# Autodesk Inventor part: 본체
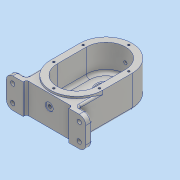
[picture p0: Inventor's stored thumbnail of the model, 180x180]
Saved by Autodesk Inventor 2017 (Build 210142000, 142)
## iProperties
Part Number: 본체
Material: 알루미늄 6061
Document SubType Name: Modeling
Designer: MRC
Density: 2.7 g/cm^3
Appearance: 알루미늄 - 평지
Mass: 756.746 g
Surface Area: 581.68 cm^2
Volume: 280.276 cm^3
Author: MRC
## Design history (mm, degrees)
sketch "스케치1"
  geometry: L1 (0, 0)-(0, -87); L2 (-40, 0)-(-40, -82); L3 (40, -82)-(40, 0); L4 (-40, -82)-(-61, -82); L5 (-61, -82)-(-61, -92); L6 (-61, -92)-(-35, -92); L7 (-35, -92)-(-35, -87); L8 (-35, -87)-(35, -87); L9 (35, -87)-(35, -92); L10 (35, -92)-(61, -92); L11 (61, -92)-(61, -82); L12 (61, -82)-(40, -82); A1 r 40 centre (0, 0) between (40, 0) and (-40, 0); 1 further point
  constraints: 26 end point, 4 parallel, 4 vertical, 2 collinear, 2 horizontal, 2 midpoint, 2 perpendicular, 2 point on circle, 2 tangent, 1 centre point
  dimensions: "d15" = 40 radius of A1; "d16" = 10 distance of L10.end L11.end; "d17" = 92 distance from line of L10 L1.start; "d18" = 70 distance of L7.end L8.end; "d19" = 122 distance between parallel lines of L11 L5; "d20" = 5 distance between parallel lines of L6 L8; "d21" = 61 distance from line of point (0, -43.5) L5
extrude "돌출1" new body sketch "스케치1" distance "d22" = 46; taper "d23" = 0 deg
sketch "스케치2"
  geometry: L1 (0, 0)-(0, -45); L2 (-40, 0)-(-40, -45); L3 (40, -45)-(40, 0); A1 r 40 centre (0, 0) between (40, 0) and (-40, 0) reference; A2 r 40 centre (0, 0) between (40, 0) and (-40, 0); A3 r 40 centre (0, -45) between (-40, -45) and (40, -45); 1 further point
  constraints: 8 end point, 4 point on circle, 4 tangent, 2 centre point, 1 concentric, 1 midpoint, 1 parallel, 1 vertical
  dimensions: "d24" = 45 distance of L1.end L1.start
extrude "돌출2" join sketch "스케치2" distance "d25" = 3; taper "d26" = 0 deg
sketch "스케치3"
  geometry: L1 (0, 0)-(0, -45); L2 (-26, 0)-(-26, -45); L3 (26, -45)-(26, 0); A1 r 40 centre (0, 0) between (40, 0) and (-40, 0) reference; A2 r 26 centre (0, 0) between (26, 0) and (-26, 0); A3 r 26 centre (0, -45) between (-26, -45) and (26, -45); 1 further point
  constraints: 8 end point, 4 point on circle, 4 tangent, 2 centre point, 1 midpoint, 1 parallel, 1 vertical
  dimensions: "d27" = 26 radius of A2; "d28" = 45 distance of L1.start L1.end
extrude "돌출3" join sketch "스케치3" distance "d29" = 11; taper "d30" = 0 deg
sketch "스케치4"
  geometry: L1 (-26, 0)-(-26, -45) reference; L2 (26, -45)-(26, 0) reference; L3 (-26, -45)-(-26, 0) reference; L4 (-26, -30)-(26, -30); A1 r 26 centre (0, 0) between (26, 0) and (-26, 0) reference
  constraints: 2 end point, 2 point on line, 1 perpendicular
  dimensions: "d31" = 30 distance from line of A1.centre L4
extrude "돌출4" cut sketch "스케치4" distance "d32" = 3; taper "d33" = 0 deg
sketch "스케치5"
  geometry: L1 (0, 0)-(0, -45); L2 (-30, 0)-(-30, -45); L3 (30, -45)-(30, 0); A1 r 40 centre (0, -45) between (-40, -45) and (40, -45) reference; A2 r 40 centre (0, 0) between (40, 0) and (-40, 0) reference; A3 r 30 centre (0, 0) between (30, 0) and (-30, 0); A4 r 30 centre (0, -45) between (-30, -45) and (30, -45); 1 further point
  constraints: 8 end point, 4 point on circle, 4 tangent, 2 centre point, 1 midpoint, 1 parallel, 1 vertical
  dimensions: "d34" = 30 radius of A3
extrude "돌출5" cut sketch "스케치5" distance "d35" = 41; taper "d36" = 0 deg
hole "구멍1" diameter "d39" = 20; stored, may be unused: countersink angle "d43" = 90 deg, drill point angle "d45" = 0 deg; dims "d40" = 6, "d41" = 28, "d42" = 8, "d44" = 12, "d46" = 10, "d47" = 10
hole "구멍2" diameter "d50" = 22; stored, may be unused: countersink angle "d54" = 90 deg, drill point angle "d56" = 0 deg; dims "d48" = 10, "d49" = 10, "d51" = 6, "d52" = 28, "d53" = 8, "d55" = 100
sketch "스케치6"
  geometry: C1 r 11 at (0, 0) reference; C2 r 14 at (0, 0); A1 r 26 centre (0, 0) between (26, 0) and (-26, 0) reference
  constraints: 1 centre point, 1 coincident
  dimensions: "d57" = 28 diameter of C2
extrude "돌출6" cut sketch "스케치6" distance "d58" = 4; taper "d59" = 0 deg
sketch "스케치8"
  geometry: L1 (0, 0)-(0, -45); L2 (35, 0)-(35, -45); L3 (-35, -45)-(-35, 0); A1 r 40 centre (0, -45) between (-40, -45) and (40, -45) reference; A2 r 40 centre (0, 0) between (40, 0) and (-40, 0) reference; A3 r 35 centre (0, 0) between (35, 0) and (-35, 0); A4 r 35 centre (0, -45) between (-35, -45) and (35, -45); 7 further points
  constraints: 8 end point, 6 point on circle, 4 coincident, 4 tangent, 2 centre point, 1 midpoint, 1 parallel, 1 vertical
  dimensions: "d60" = 35 radius of A3
hole "구멍3" sketch "스케치8" at (0, 35), (-35, 0), (35, 0), (35, -45), (-35, -45), (0, -80) diameter "d61" = 3.242; stored, may be unused: countersink angle "d65" = 90 deg, drill point angle "d67" = 118 deg; dims "d62" = 8, "d63" = 28, "d64" = 8, "d66" = 10
node "작업 평면1"
sketch "스케치9"
  geometry: C1 r 6 at (0, 28); 1 further point
  constraints: 1 centre point
  dimensions: "d69" = 12 diameter of C1; "d70" = 28 distance of C1.centre point (0, 0)
extrude "돌출7" join sketch "스케치9" stored distance "d71" = 4; taper "d72" = 0 deg
sketch "스케치10"
  geometry: C1 r 6 at (0, 0) reference; 2 further points
  constraints: 1 coincident
hole "구멍4" sketch "스케치10" at (0, 0) diameter "d73" = 4.917; stored, may be unused: countersink angle "d77" = 90 deg, drill point angle "d79" = 0 deg; dims "d74" = 12, "d75" = 28, "d76" = 8, "d78" = 17.1
sketch "스케치12"
  geometry: L1 (0, 0)-(70, 0) reference; L2 (75, 49)-(-5, 49) reference; 3 further points
  constraints: 1 midpoint, 1 vertical alignment
  dimensions: "d88" = 21 distance from line of point (35, 28) L2
hole "구멍5" sketch "스케치12" at (35, 28) diameter "d81" = 4.917; stored, may be unused: countersink angle "d85" = 90 deg, drill point angle "d87" = 0 deg; dims "d82" = 12, "d83" = 12, "d84" = 1, "d86" = 17.1
fillet "모깎기1" dims "d89" = 10
hole "구멍6" diameter "d92" = 6.6; stored, may be unused: countersink angle "d96" = 90 deg, drill point angle "d98" = 0 deg; dims "d90" = 10, "d91" = 10, "d93" = 12, "d94" = 11, "d95" = 2, "d97" = 17.1
hole "구멍7" diameter "d101" = 6.6; stored, may be unused: countersink angle "d105" = 90 deg, drill point angle "d107" = 0 deg; dims "d99" = 10, "d100" = 10, "d102" = 12, "d103" = 11, "d104" = 2, "d106" = 17.1
hole "구멍8" diameter "d110" = 6.6; stored, may be unused: countersink angle "d114" = 90 deg, drill point angle "d116" = 0 deg; dims "d108" = 10, "d109" = 10, "d111" = 12, "d112" = 11, "d113" = 2, "d115" = 17.1
hole "구멍9" diameter "d119" = 6.6; stored, may be unused: countersink angle "d123" = 90 deg, drill point angle "d125" = 0 deg; dims "d117" = 10, "d118" = 10, "d120" = 12, "d121" = 11, "d122" = 2, "d124" = 17.1
fillet "모깎기3" dims "d130" = 3
fillet "모깎기2" dims "d126" = 3
chamfer "모따기1" distance "d127" = 1; stored, may be unused: second distance "d128" = 2, angle "d129" = 45 deg
fillet "모깎기4" dims "d131" = 3
fillet "모깎기5" dims "d132" = 0.3
chamfer "모따기2" distance "d133" = 1; stored, may be unused: second distance "d134" = 2, angle "d135" = 45 deg
fillet "모깎기6" dims "d136" = 3
fillet "모깎기7" dims "d137" = 3
sketch "스케치13"
  geometry: L1 (-51, -92)-(-61, -92) reference; 1 further point
  constraints: 1 other
  dimensions: "d138" = 12 distance from line of L1 point (-0.116, -80)
feature "엠보싱1" sketch "스케치13" dims "d15" = 40, "d16" = 10, "d17" = 92, "d18" = 70, "d19" = 122, "d20" = 5, "d21" = 61, "d24" = 45, "d139" = 0.5, "d140" = 0
sketch "스케치14"
  geometry: A1 r 26 centre (0, 0) between (26, 0) and (-26, 0) reference; 1 further point
  constraints: 1 vertical alignment
  dimensions: "d141" = 20 distance of point (0, 20) A1.centre
hole "구멍10" sketch "스케치14" at (0, 20) diameter "d142" = 3.242; stored, may be unused: countersink angle "d146" = 90 deg, drill point angle "d148" = 118 deg; dims "d143" = 8, "d144" = 11, "d145" = 2, "d147" = 10
fillet "모깎기8" dims "d152" = 5
node "솔리드1"
pattern_circular "원형 패턴1" dims angle "d150" = 360 deg
other parameters: "d68" = 43
